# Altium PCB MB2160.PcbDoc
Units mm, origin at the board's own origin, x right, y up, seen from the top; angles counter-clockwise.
Board outline 60 x 59.3 mm, 2 copper layers (Top Layer, Bottom Layer), stack 1.57 mm thick; 35 components, 32 nets, 189 pads, 146 vias.
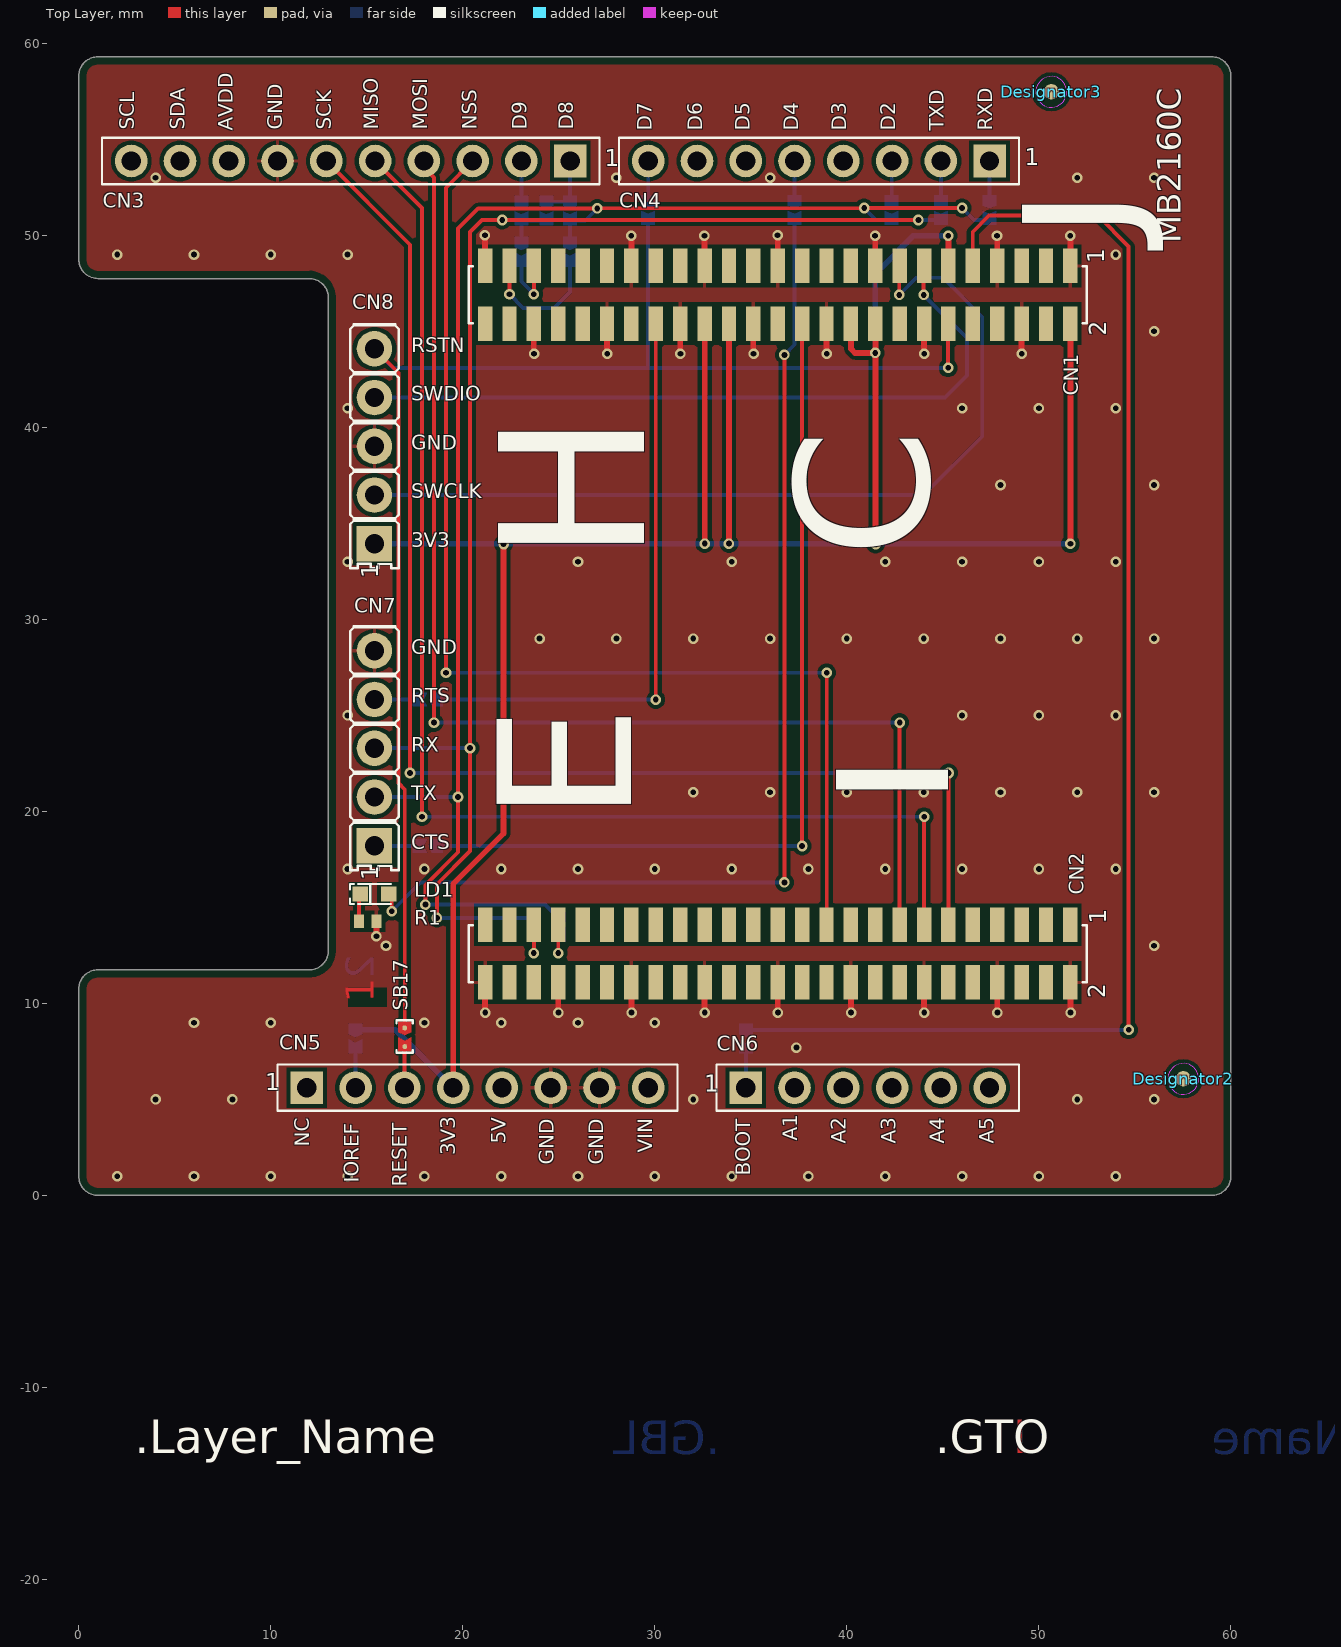
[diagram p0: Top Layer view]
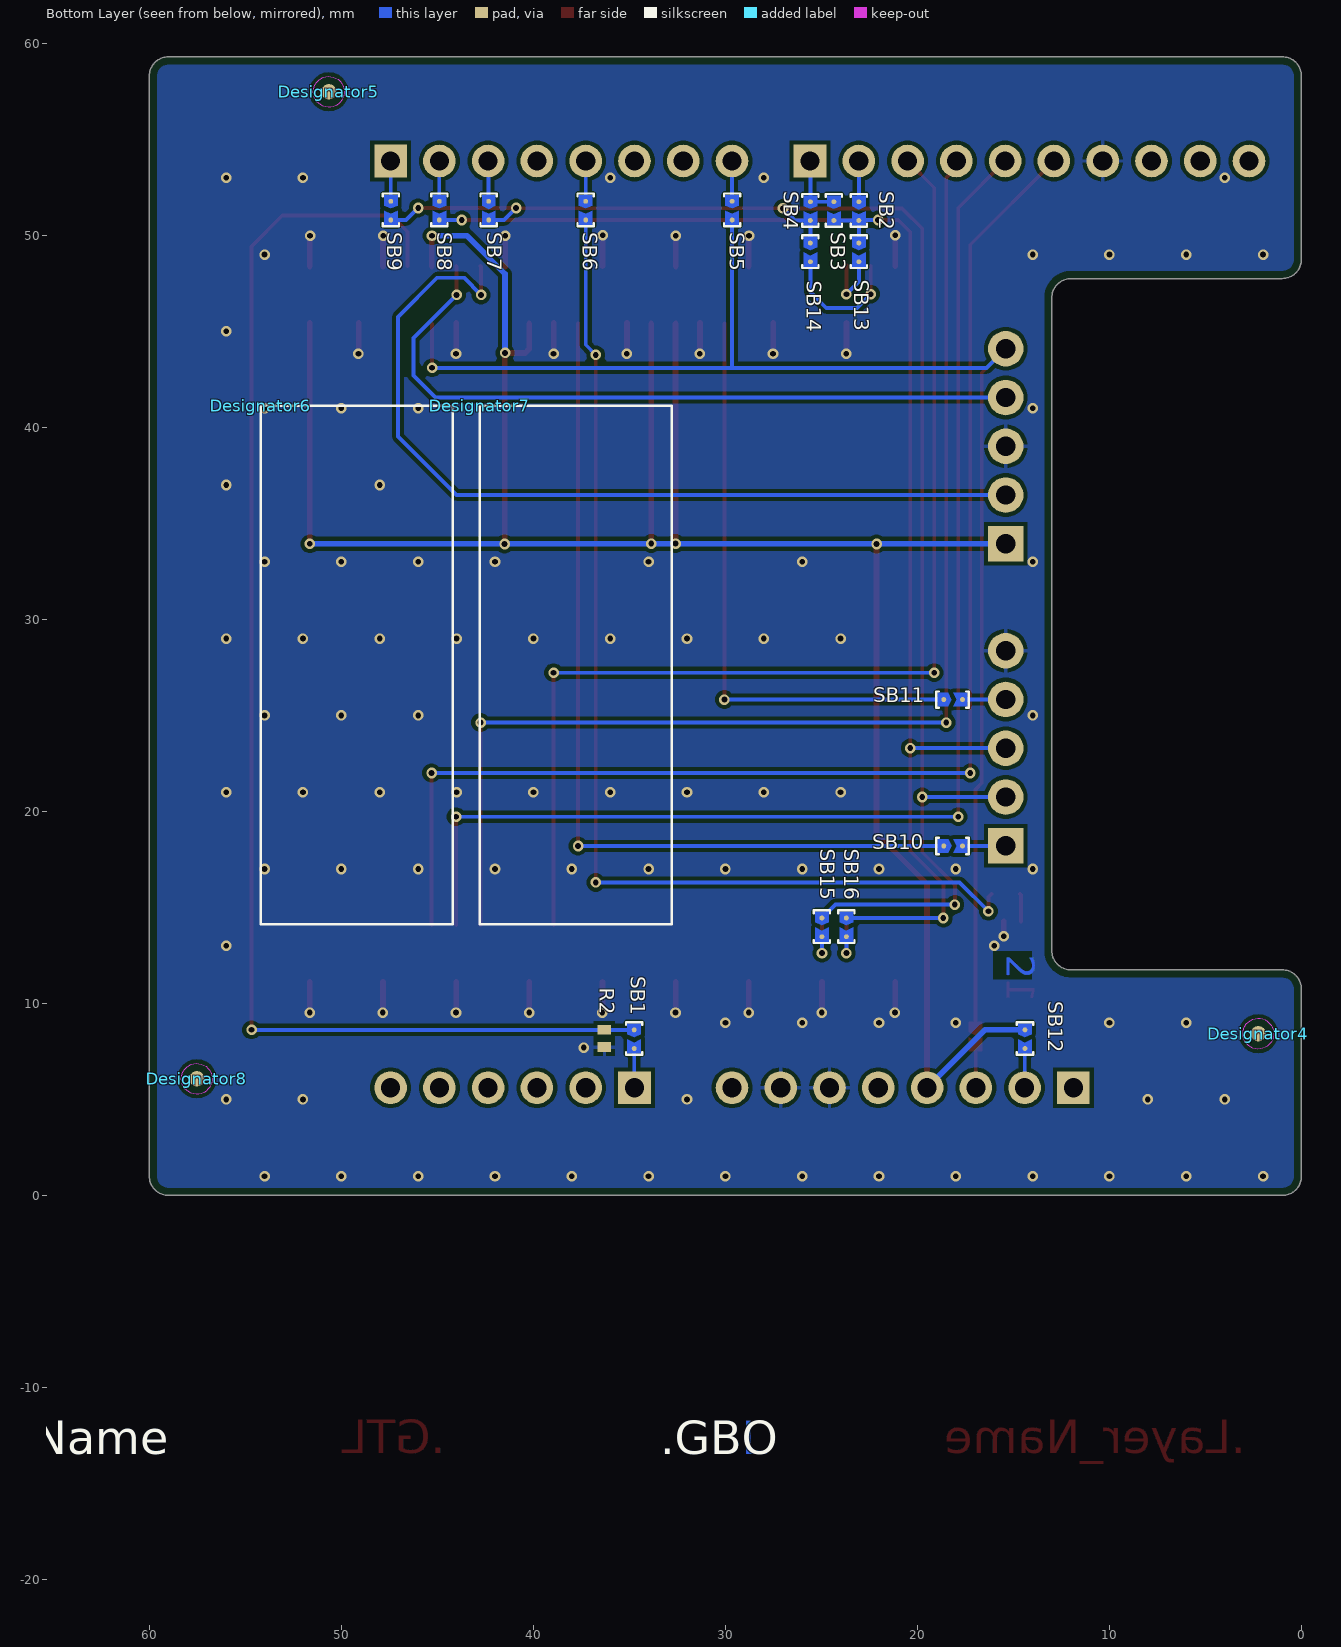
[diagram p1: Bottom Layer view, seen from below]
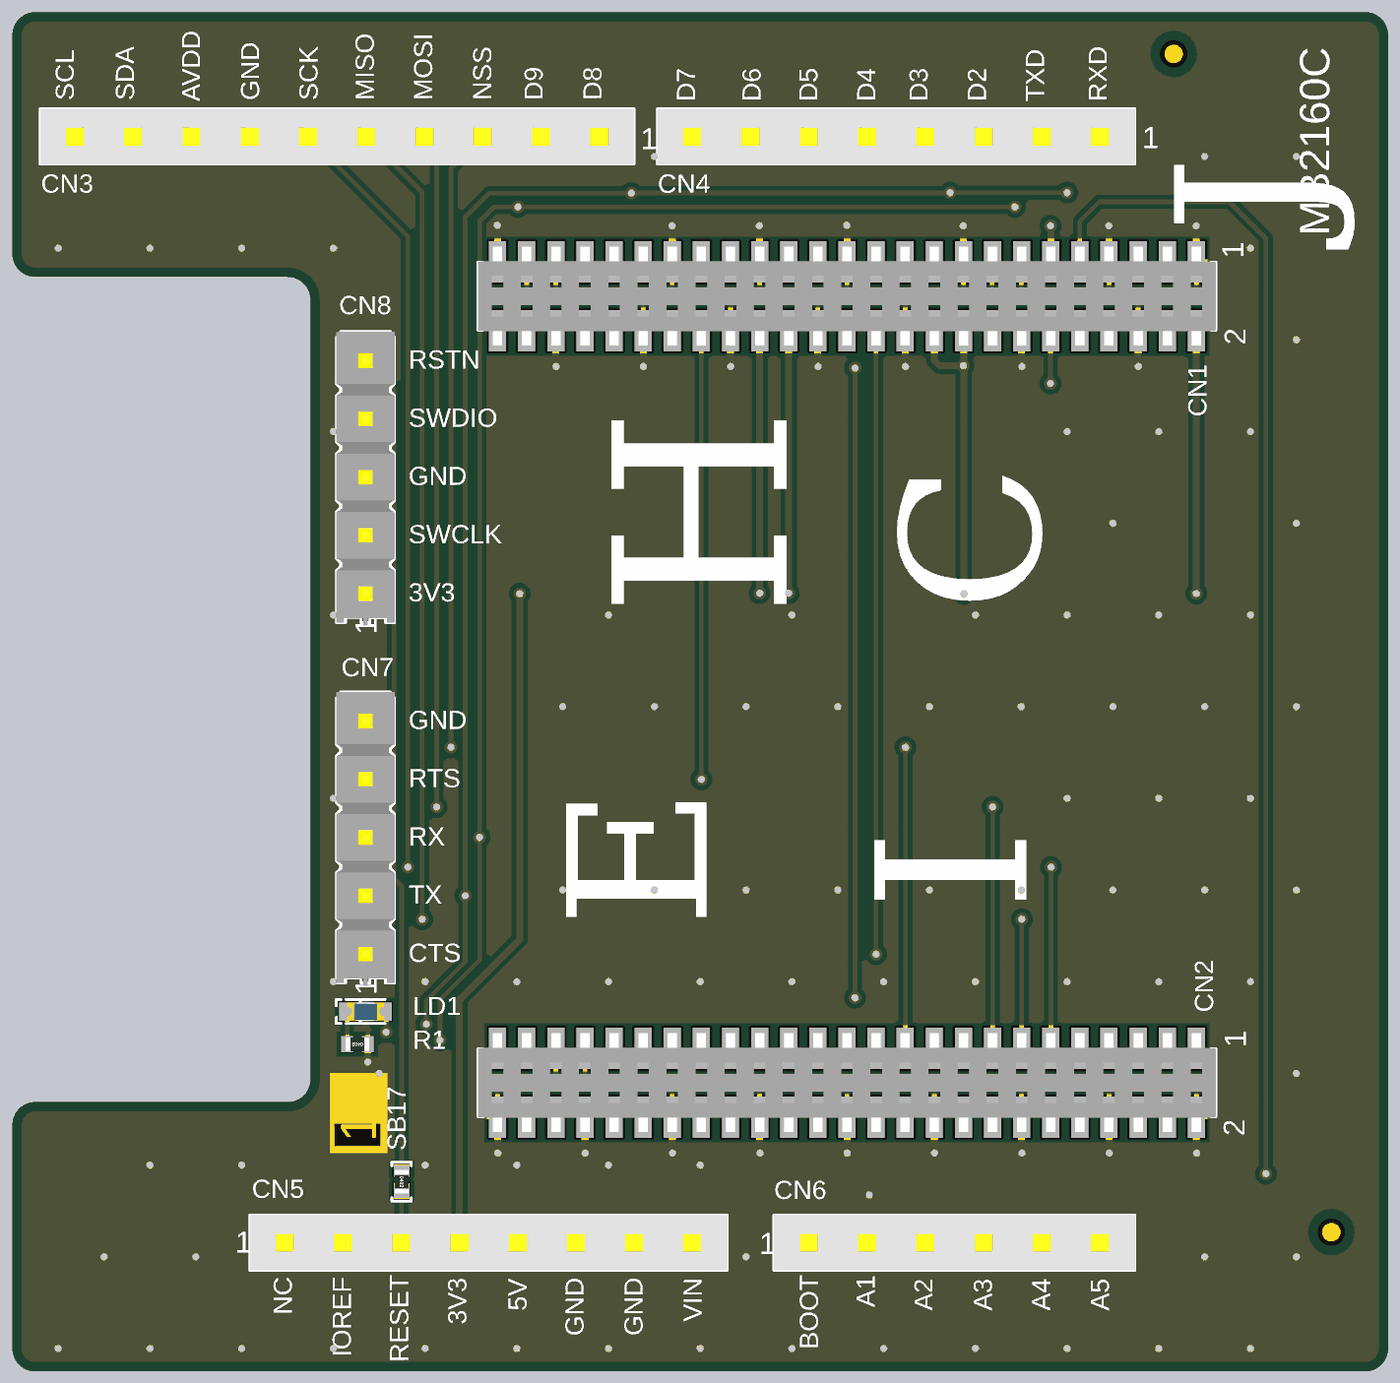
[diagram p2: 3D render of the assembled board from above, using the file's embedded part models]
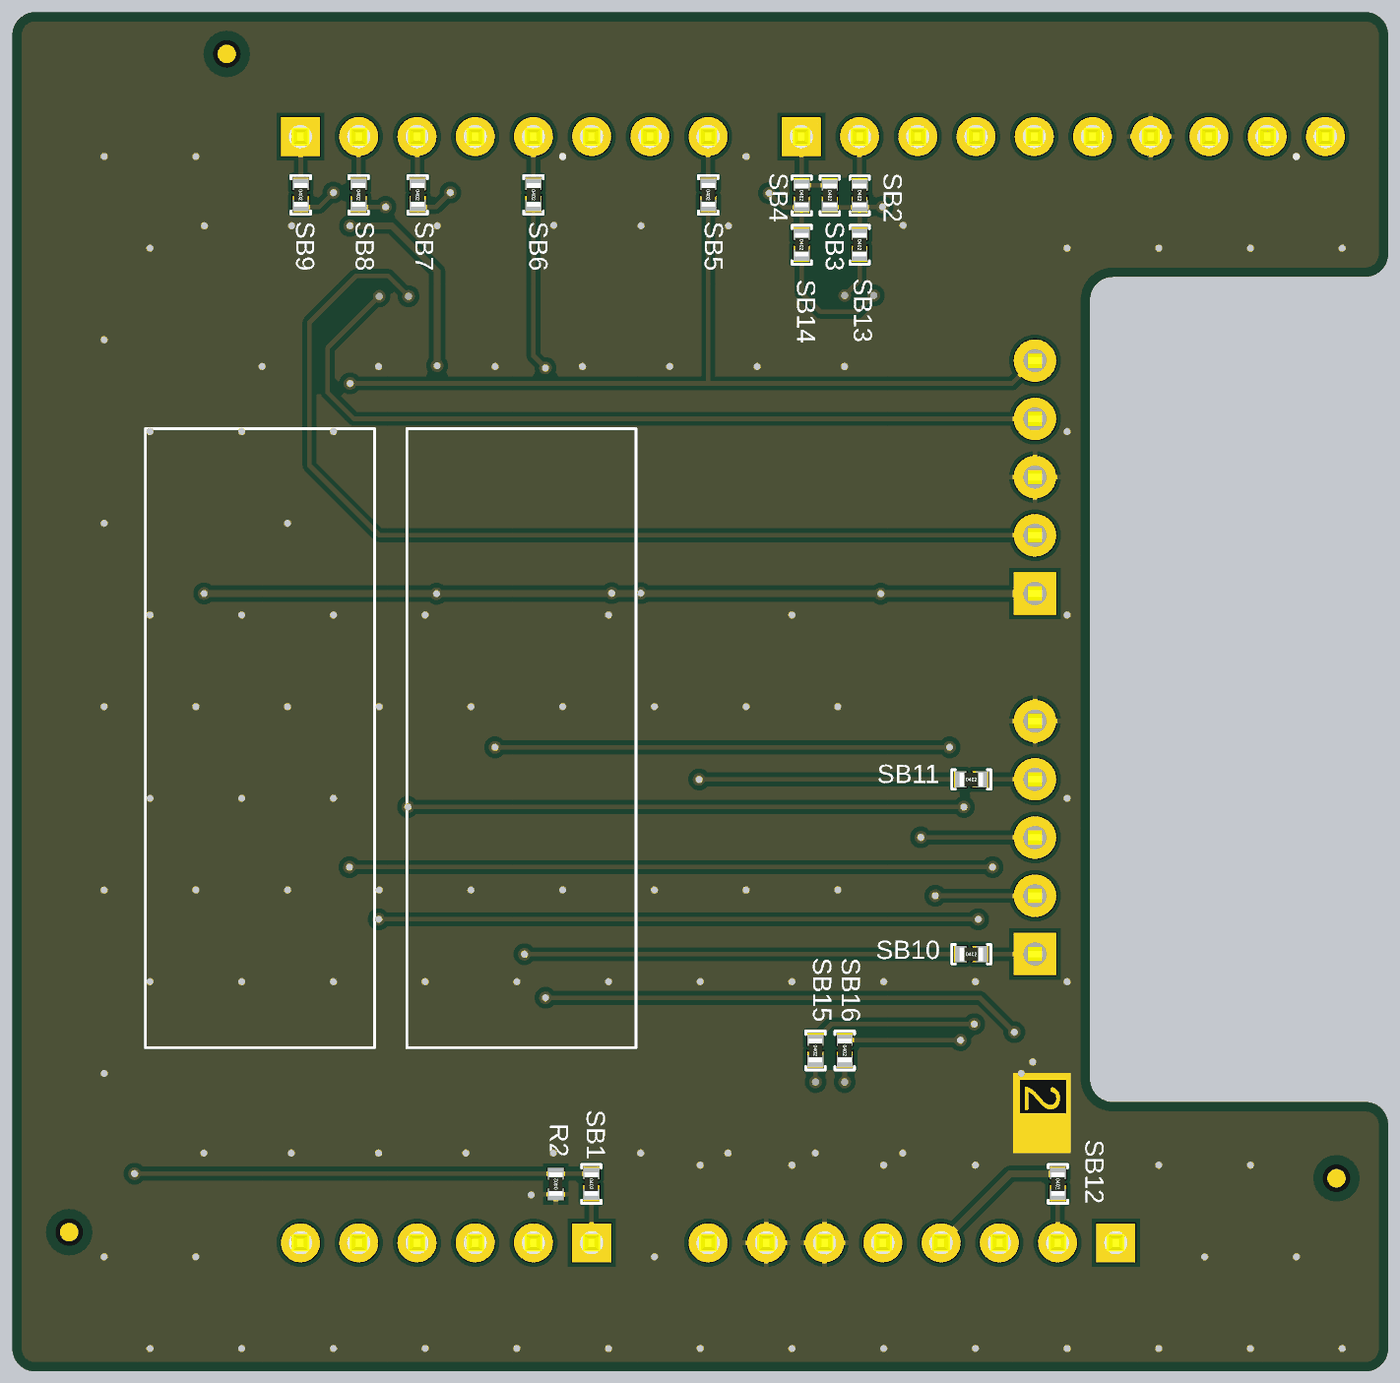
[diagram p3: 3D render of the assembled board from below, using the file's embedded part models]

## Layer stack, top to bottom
Top Solder: solder mask 0.015, Solder Resist, Dk 3.5
Top Layer: signal copper 0.035
Dielectric 1: dielectric 1.5, FR-4, Dk 4.8
Bottom Layer: signal copper 0.035
Bottom Solder: solder mask 0.015, Solder Resist, Dk 3.5

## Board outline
0,1 ccw(c1,1) 1,0 59,0 ccw(c59,1) 60,1 60,58.3 ccw(c59,58.3) 59,59.3 1,59.3 ccw(c1,58.3) 0,58.3 0,48.75 ccw(c1,48.75) 1,47.75 12,47.75 cw(c12,46.75) 13,46.75 13,12.75 cw(c12,12.75) 12,11.75 1,11.75 ccw(c1,10.75) 0,10.75

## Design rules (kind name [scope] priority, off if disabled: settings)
BoardOutlineClearance [All] p1: gap=0.4 ignorepadtopadclearanceinfootprint=FALSE
Clearance [All] p1: gap=0.2 ignorepadtopadclearanceinfootprint=FALSE except(0: Arc-Hole Track-Hole SMDPad-Hole THPad-Hole Via-Hole Fill-Hole Poly-Hole Region-Hole Text-Hole)
ComponentClearance [All] p1: gap=0.2 collisioncheckmode=3 verticalgap=0.2 showdistances=FALSE
HoleSize [All] p1: absolutevalues=TRUE maxlimit=10 minlimit=0.025 maxpercent=80.000 minpercent=20.000
MinimumSolderMaskSliver [All] p1: minsoldermaskwidth=0.1
PlaneConnect [All] p1: planeconnectstyle=Relief reliefexpansion=0.508 reliefentries=4 reliefconductorwidth=0.21 reliefairgap=0.21
PolygonConnect PolygonConnect_via [IsVia] p1: connectstyle=Direct reliefconductorwidth=0.254 reliefentries=4 polygonreliefangle="90 Angle" airgapwidth=0.254
PolygonConnect [All] p2: connectstyle=Relief reliefconductorwidth=0.2 reliefentries=4 polygonreliefangle="90 Angle" airgapwidth=0.2
RoutingVias [All] p1: holewidth=0.3 width=0.55 viastyle="Through Hole" minholewidth=0.3 minwidth=0.55 maxholewidth=0.3 maxwidth=0.55 viatemplateguid#1={C2BB52C7-2357-484C-AD71-DC781CB2D949} viatemplatename#1=v55h30m0mx0(1)
SilkToSilkClearance [All] p1 off: silktosilkclearance=0.254
SilkToSolderMaskClearance [IsPad] p1 off: minsilkscreentomaskgap=0.254 clearancetoexposedcopper=TRUE
SolderMaskExpansion [All] p1: expansion=0.102 istentingtop=FALSE
SupplyNets "Schematic Supply Nets_2" [InNet('IOREF')] p1: voltage=0.000
SupplyNets "Schematic Supply Nets_1" [InNet('3V3')] p2: voltage=0.000
SupplyNets "Schematic Supply Nets" [InNet('GND')] p3: voltage=0.000
Width [All] p1: maxlimit=1 minlimit=0.2 preferedwidth=0.2 minimp=50.000000 maximp=50.000000 favimp=50.000000
24 further rules are at their usual default settings.

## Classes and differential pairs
component class Connectors: CN1 CN2 CN3 CN4 CN5 CN6 CN7 CN8 LD1 R1 R2 SB1 SB2 SB3 SB4 SB5 SB6 SB7 SB8 SB9 SB10 SB11 SB12 SB13 SB14 SB15 SB16 SB17

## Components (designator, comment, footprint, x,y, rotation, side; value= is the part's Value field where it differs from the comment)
CN1 "CLP-125-02-F-D" CON_SAMTEC_CLP-125-02-F-D 36.4,46.907 r270 top value="Socket 25x2"
CN2 "CLP-125-02-F-D" CON_SAMTEC_CLP-125-02-F-D 36.4,12.593 r270 top value="Socket 25x2"
CN3 "Socket 10x1" CON_SAMTEC_SSQ-110-03-F-S 14.162,53.871 r180 top
CN4 "Socket 8x1" CON_SAMTEC_SSQ-108-03-F-S 38.546,53.871 r180 top
CN5 "Socket 8x1" CON_SAMTEC_SSQ-108-03-F-S 20.766,5.611 r0 top
CN6 "Socket 6x1" CON_SAMTEC_SSQ-106-03-F-S 41.086,5.611 r0 top
CN7 "Header 5x1" CON_SAMTEC_TSW-105-07-X-S 15.4,23.29 r90 top
CN8 "Header 5x1" CON_SAMTEC_TSW-105-07-X-S 15.4,39.015 r90 top
Designator2 "Comment" MIRE_PLACE_SMD_0P8MM 57.525,6.075 r180 top
Designator3 "Comment" MIRE_PLACE_SMD_0P8MM 50.65,57.475 r180 top
Designator4 "Comment" MIRE_PLACE_SMD_0P8MM 2.25,8.425 r0 bottom
Designator5 "Comment" MIRE_PLACE_SMD_0P8MM 50.65,57.475 r0 bottom
Designator6 "Comment" LOGO_ETIQUETTE 54.2,41.125 r270 bottom
Designator7 "Comment" LOGO_ETIQUETTE 42.8,41.125 r270 bottom locked
Designator8 "Comment" MIRE_PLACE_SMD_0P8MM 57.525,6.075 r0 bottom
LD1 "LED_blue" LED_0603_OSRAM_LB-Q39G-L2OO-35-1_BLUE_1A2K_H0P4 15.4,15.7 r180 top value=Blue
R1 "Resistor" R0402 15.05,14.275 r180 top value=680R
R2 "Resistor" R0402 36.3,8.175 r90 bottom value=100K
SB1 "SB_ON" SOLDER-BRIDGE_R0402-0R 34.75,8.175 r270 bottom value=0R
SB2 "SB_ON" SOLDER-BRIDGE_R0402-0R 23.05,51.3 r270 bottom value=0R
SB3 "SB_ON" SOLDER-BRIDGE_R0402-0R 24.35,51.3 r270 bottom value=0R
SB4 "SB_ON" SOLDER-BRIDGE_R0402-0R 25.575,51.3 r270 bottom value=0R
SB5 "SB_ON" SOLDER-BRIDGE_R0402-0R 29.65,51.325 r270 bottom value=0R
SB6 "SB_ON" SOLDER-BRIDGE_R0402-0R 37.275,51.325 r270 bottom value=0R
SB7 "SB_ON" SOLDER-BRIDGE_R0402-0R 42.325,51.325 r270 bottom value=0R
SB8 "SB_ON" SOLDER-BRIDGE_R0402-0R 44.9,51.325 r270 bottom value=0R
SB9 "SB_ON" SOLDER-BRIDGE_R0402-0R 47.425,51.325 r270 bottom value=0R
SB10 "SB_ON" SOLDER-BRIDGE_R0402-0R 18.175,18.2 r180 bottom value=0R
SB11 "SB_ON" SOLDER-BRIDGE_R0402-0R 18.175,25.825 r180 bottom value=0R
SB12 "SB_ON" SOLDER-BRIDGE_R0402-0R 14.4,8.175 r270 bottom value=0R
SB13 "SB_ON" SOLDER-BRIDGE_R0402-0R 23.05,49.15 r270 bottom value=0R
SB14 "SB_ON" SOLDER-BRIDGE_R0402-0R 25.575,49.15 r270 bottom value=0R
SB15 "SB_ON" SOLDER-BRIDGE_R0402-0R 24.975,14 r270 bottom value=0R
SB16 "SB_ON" SOLDER-BRIDGE_R0402-0R 23.7,14 r270 bottom value=0R
SB17 "SB_ON" SOLDER-BRIDGE_R0402-0R 16.975,8.275 r270 top value=0R

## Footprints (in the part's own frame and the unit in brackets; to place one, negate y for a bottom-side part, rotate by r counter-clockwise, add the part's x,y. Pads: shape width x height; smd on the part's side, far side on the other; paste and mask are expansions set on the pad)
CON_SAMTEC_CLP-125-02-F-D [mm] "MCD-02705"
  rect 1.8x0.75 smd: 1(-1.5,15.24) 2(1.5,15.24) 3(-1.5,13.97) 4(1.5,13.97) 5(-1.5,12.7) 6(1.5,12.7) 7(-1.5,11.43) 8(1.5,11.43) 9(-1.5,10.16) 10(1.5,10.16) 11(-1.5,8.89) 12(1.5,8.89) 13(-1.5,7.62) 14(1.5,7.62) 15(-1.5,6.35) 16(1.5,6.35) 17(-1.5,5.08) 18(1.5,5.08) 19(-1.5,3.81) 20(1.5,3.81) 21(-1.5,2.54) 22(1.5,2.54) 23(-1.5,1.27) 24(1.5,1.27) 25(-1.5,0) 26(1.5,0) 27(-1.5,-1.27) 28(1.5,-1.27) 29(-1.5,-2.54) 30(1.5,-2.54) 31(-1.5,-3.81) 32(1.5,-3.81) 33(-1.5,-5.08) 34(1.5,-5.08) 35(-1.5,-6.35) 36(1.5,-6.35) 37(-1.5,-7.62) 38(1.5,-7.62) 39(-1.5,-8.89) 40(1.5,-8.89) 41(-1.5,-10.16) 42(1.5,-10.16) 43(-1.5,-11.43) 44(1.5,-11.43) 45(-1.5,-12.7) 46(1.5,-12.7) 47(-1.5,-13.97) 48(1.5,-13.97) 49(-1.5,-15.24) 50(1.5,-15.24)
  silkscreen extent -1.48,-16.09 1.49,16.09, body extent -2.16,-16.09 2.16,16.09, height 2.27
CON_SAMTEC_SSQ-106-03-F-S [mm] "MCD-02623"
  rect 1.7x1.7 hole 1 mask+0.05: 1(-6.35,0)
  round 1.7 hole 1 mask+0.05: 2(-3.81,0) 3(-1.27,0) 4(1.27,0) 5(3.81,0) 6(6.35,0)
  silkscreen extent -7.88,-1.21 7.88,1.21, body extent -7.87,-1.21 7.87,1.21, height 8.51
CON_SAMTEC_SSQ-108-03-F-S [mm] "MCD-02624"
  rect 1.7x1.7 hole 1 mask+0.05: 1(-8.89,0)
  round 1.7 hole 1 mask+0.05: 2(-6.35,0) 3(-3.81,0) 4(-1.27,0) 5(1.27,0) 6(3.81,0) 7(6.35,0) 8(8.89,0)
  silkscreen extent -10.41,-1.21 10.41,1.21, body extent -10.41,-1.21 10.41,1.21, height 8.51
CON_SAMTEC_SSQ-110-03-F-S [mm] "MCD-02625"
  rect 1.7x1.7 hole 1 mask+0.05: 1(-11.43,0)
  round 1.7 hole 1 mask+0.05: 2(-8.89,0) 3(-6.35,0) 4(-3.81,0) 5(-1.27,0) 6(1.27,0) 7(3.81,0) 8(6.35,0) 9(8.89,0) 10(11.43,0)
  silkscreen extent -12.95,-1.21 12.95,1.21, body extent -12.95,-1.21 12.95,1.21, height 8.51
CON_SAMTEC_TSW-105-07-X-S [mm] "MCD-02060"
  rect 1.85x1.85 hole 1 mask+0.05: 1(-5.08,0)
  round 1.85 hole 1 mask+0.05: 2(-2.54,0) 3(0,0) 4(2.54,0) 5(5.08,0)
  silkscreen extent -6.35,-1.27 6.35,1.27, body extent -6.48,-1.27 6.35,1.27, height 8.38
LED_0603_OSRAM_LB-Q39G-L2OO-35-1_BLUE_1A2K_H0P4 [mm]
  rect 0.8x0.8 smd mask+0.05: 1(-0.75,0) 2(0.75,0)
  silkscreen extent -0.85,-0.53 1.28,0.53, body extent -0.85,-0.45 0.85,0.45, height 0.6
LOGO_ETIQUETTE [mm]
  silkscreen extent 0,0 27,10
MIRE_PLACE_SMD_0P8MM [mm]
  round 0.8 smd paste-10 mask+0.2: 1(0,0)
  Top Layer keep-out circle w0.01: c0,0 r0.804
R0402 [mm]
  rect 0.51x0.7 smd mask+0.05: 1(-0.45,0) 2(0.45,0)
  body extent -0.52,-0.3 0.52,0.3, height 0.4
SOLDER-BRIDGE_R0402-0R [mil] "MCD-01619"
  round 10 smd paste-393.7: 1(-17.72,0) 2(20.67,0)
  Top Layer region: 1.48,13.78 8.37,0 1.48,-13.78 30.51,-13.78 30.51,13.78
  Top Layer region: -30.51,-13.78 -30.51,13.78 -8.86,13.78 -2.95,0 -8.86,-13.78
  silkscreen extent -33,-17 33,17, body extent -20,-12 20,12, height 14

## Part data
CN1 CN2: library part MCD-02705, "Socket, 25x2, 1.27mm, VR, SMD, T=2.29mm", Manufacturer=SAMTEC
CN3: library part MCD-02625, "Socket, 10x1, 2.54mm, VR, TH, T=8.51mm/10mm", Manufacturer=SAMTEC, Manufacturer_Part_Number=SSQ-110-03-F-S
CN4 CN5: library part MCD-02624, "Socket, 8x1, 2.54mm, VR, TH, T=8.51mm/10mm", Manufacturer=SAMTEC, Manufacturer_Part_Number=SSQ-108-03-F-S
CN6: library part MCD-02623, "Socket, 6x1, 2.54mm, VR, TH, T=8.51mm/10mm", Manufacturer=SAMTEC, Manufacturer_Part_Number=SSQ-106-03-F-S
CN7 CN8: library part MCD-02060, "Header, 5x1, 2.54mm, VR, TH, T=5.84mm/2.54mm", Manufacturer=SAMTEC, Manufacturer_Part_Number=TSW-105-07-G-S
LD1: library part MCD-00585, "LED, Blue, 2V85, 5mA, 0603", Manufacturer="OSRAM OPTO SEMICONDUCTORS", Manufacturer_Part_Number="LB Q39G-L2OO-35-1", Package=0603
R1: library part MCD-00507, "Resistor, 680R, 0402, +/-1%, 1/16W", Manufacturer=YAGEO, Manufacturer_Part_Number=RC0402FR-07680RL, Package=0402
R2: library part MCD-00059, "Resistor, 100K, 0402, +/-1%, 1/16W", Manufacturer=YAGEO, Manufacturer_Part_Number=RC0402FR-07100KL, Package=0402
SB1 SB2 SB3 SB4 SB5 SB6 SB7 SB8 SB9 SB10 SB11 SB12 SB13 SB14 SB15 SB16 SB17: library part MCD-01618, "Resistor, 0R, SB0402, 5%, 0.063W", Manufacturer=YAGEO, Manufacturer_Part_Number=RC0402JR-070RL, Package=0402

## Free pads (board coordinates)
  round 0.508 on Mech16: 1(14.573,-20.356) 1(63.421,-20.356)

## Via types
v1: diameter 0.55, hole 0.3, Top Layer to Bottom Layer, tented both sides, 146 vias

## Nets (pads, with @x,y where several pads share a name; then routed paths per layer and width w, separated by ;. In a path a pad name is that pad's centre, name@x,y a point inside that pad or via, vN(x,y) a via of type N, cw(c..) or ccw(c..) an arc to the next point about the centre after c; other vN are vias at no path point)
3V3: CN1.2 CN1.11 CN1.18 CN1.20 CN1.30 CN1.32 CN5.4 CN8.1 SB12.1 | length 130.6
  Top Layer w0.3: CN5.4 19.496,16.221 22.125,18.85 v1(22.125,33.925) ; CN1.32 32.595,45.402 v1(32.595,33.95) ; v1(33.86,33.95) CN1.30 ; CN1.20 40.21,44.09 40.425,43.875 v1(41.475,43.875) ; CN1.18 41.49,45.397 41.49,33.935 v1(41.5,33.925) ; CN1.11@45.29,48.383 CN1.11 v1@45.29,49.966 ; v1(51.64,33.935) CN1.2 CN1.2@51.64,45.431
  Bottom Layer w0.3: 14.7,8.625 16.482,8.625 CN5.4 ; CN8.1 v1(51.64,33.935) ; v1(41.475,43.875) 41.475,47.994 43.457,49.976 v1(45.28,49.976)
BOOT: CN1.9 R2.2 SB1.1 | length 71.6
  Top Layer w0.2: CN1.9 46.56,50.185 47.4,51.025 53.075,51.025 54.675,49.425 v1(54.675,8.625)
  Bottom Layer w0.2: SB1.1 v1(54.675,8.625)
GND: CN1.1 CN1.6 CN1.7 CN1.14 CN1.17 CN1.22 CN1.25 CN1.28 CN1.31 CN1.34 CN1.37 CN1.40 CN1.46 CN1.49 CN2.2 CN2.8 CN2.14 CN2.20 CN2.26 CN2.32 CN2.38 CN2.44 CN2.50 CN3.7 CN5.6 CN5.7 CN7.5 CN8.3 R1.1 R2.1 | length 37.5
  Top Layer w0.3: v1(15.5,13.5) R1.1 ; v1(21.15,50) 21.16,49.99 CN1.49 ; CN2.50@21.16,11.117 21.16,9.534 v1(21.17,9.524) ; CN1.46@23.7,45.431 23.7,43.848 v1(23.71,43.838) ; CN2.44@24.97,11.117 24.97,9.534 v1(24.98,9.524) ; CN1.40@27.51,45.431 27.51,43.848 v1(27.52,43.838) ; v1(28.77,49.976) 28.78,49.966 CN1.37@28.78,48.383 ; CN2.38@28.78,11.117 28.78,9.534 v1(28.79,9.524) ; CN1.34@31.32,45.431 31.32,43.848 v1(31.33,43.838) ; v1(32.58,49.976) 32.59,49.966 CN1.31@32.59,48.383 ; CN2.32@32.59,11.117 32.59,9.534 v1(32.6,9.524) ; CN1.28@35.13,45.431 35.13,43.848 v1(35.14,43.838) ; v1(36.39,50) 36.4,49.99 CN1.25 ; CN2.26@36.4,11.117 36.4,9.534 v1(36.41,9.524) ; CN1.22@38.94,45.431 38.94,43.848 v1(38.95,43.838) ; CN2.20@40.21,11.117 40.21,9.534 v1(40.22,9.524) ; v1(41.47,49.976) 41.48,49.966 CN1.17@41.48,48.383 ; CN2.14@44.02,11.117 44.02,9.534 v1(44.03,9.524) ; CN1.14@44.02,45.431 44.02,43.848 v1(44.03,43.838) ; v1(47.82,49.976) 47.83,49.966 CN1.7@47.83,48.383 ; CN2.8@47.83,11.117 47.83,9.534 v1(47.84,9.524) ; CN1.6@49.1,45.431 49.1,43.848 v1(49.11,43.838) ; v1(51.63,49.976) 51.64,49.966 CN1.1@51.64,48.383 ; CN2.2@51.64,11.117 51.64,9.534 v1(51.65,9.524)
  other v1: 2,1 6,1 10,1 14,1 18,1 22,1 26,1 30,1 34,1 38,1 42,1 46,1 50,1 54,1 4,5 8,5 32,5 52,5 56,5 37.375,7.7 6,9 10,9 18,9 22,9 26,9 30,9 16,13 56,13 14,17 18,17 22,17 26,17 30,17 34,17 38,17 42,17 46,17 50,17 54,17 24,21 28,21 32,21 36,21 40,21 44,21 48,21 52,21 56,21 14,25 46,25 50,25 54,25 24,29 28,29 32,29 36,29 40,29 44,29 48,29 52,29 56,29 14,33 26,33 34,33 42,33 46,33 50,33 54,33 48,37 56,37 14,41 46,41 50,41 54,41 56,45 2,49 6,49 10,49 14,49 54,49 4,53 28,53 36,53 52,53 56,53
IOREF: CN5.2 SB12.2 | length 2
  Bottom Layer w0.2: SB12.2 14.408,7.642 14.408,5.619 CN5.2
LED: LD1.1 SB6.2 | length 56.8
  Top Layer w0.2: LD1.1 16.3,15.55 v1(16.3,14.8) ; v1(36.75,16.3) v1(36.75,43.775)
  Bottom Layer w0.2: v1(16.3,14.8) 17.8,16.3 v1(36.75,16.3) ; v1(36.75,43.775) 37.275,44.3 SB6.2
MISO: CN2.13 CN3.5 | length 66.9
  Top Layer w0.2: CN3.5 17.875,51.428 v1(17.875,19.725) ; CN2.13 44.025,14.098 v1(44.025,19.725)
  Bottom Layer w0.2: v1(17.875,19.725) v1(44.025,19.725)
MOSI: CN2.15 CN3.4 | length 64.2
  Top Layer w0.2: CN3.4 17.972,53.532 18.5,53.004 v1(18.5,24.625) ; CN2.15 v1(42.75,24.625)
  Bottom Layer w0.2: v1(18.5,24.625) v1(42.75,24.625)
NetCN1_24: CN1.24 SB10.1 | length 46.3
  Top Layer w0.2: v1(37.67,18.2) CN1.24
  Bottom Layer w0.2: SB10.1 v1@37.675,18.2
NetCN1_36: CN1.36 SB11.1 | length 31
  Top Layer w0.2: v1(30.05,25.825) CN1.36
  Bottom Layer w0.2: SB11.1 v1(30.05,25.825)
NetCN1_45: CN1.45 SB13.2 | length 3.4
  Top Layer w0.2: v1(23.7,46.938) CN1.45 CN1.45@23.7,48.431
  Bottom Layer w0.2: SB13.2 23.05,47.588 v1(23.7,46.938)
NetCN1_47: CN1.47 SB14.2 | length 6.8
  Top Layer w0.2: v1(22.43,46.938) CN1.47
  Bottom Layer w0.2: v1(22.43,46.938) 23.143,46.225 24.75,46.225 25.575,47.05 SB14.2
NetCN2_43: CN2.43 SB15.2 | length 2.3
  Top Layer w0.2: v1(24.97,12.624) CN2.43
  Bottom Layer w0.2: v1(24.97,12.624) 24.973,12.626 24.973,13.473 SB15.2
NetCN2_45: CN2.45 SB16.2 | length 2.3
  Top Layer w0.2: v1(23.7,12.624) CN2.45
  Bottom Layer w0.2: v1(23.7,12.624) SB16.2
NetCN3_1: CN3.1 SB3.1 SB4.1 | length 3.4
  Bottom Layer w0.2: SB3.1 SB4.1 25.575,53.854 CN3.1
NetCN3_2: CN3.2 SB2.1 | length 2.1
  Bottom Layer w0.2: SB2.1 SB2.1 23.051,53.87 CN3.2
NetCN4_1: CN4.1 SB9.1 | length 2.1
  Bottom Layer w0.2: SB9.1 47.425,53.86 CN4.1
NetCN4_2: CN4.2 SB8.1 | length 2.1
  Bottom Layer w0.2: CN4.2 44.898,53.869 44.898,51.777 SB8.1
NetCN4_3: CN4.3 SB7.1 | length 2.1
  Bottom Layer w0.2: SB7.1 42.335,51.785 42.335,53.85 CN4.3
NetCN4_5: CN4.5 SB6.1 | length 2.1
  Bottom Layer w0.2: SB6.1@37.276,51.775 CN4.5
NetCN4_8: CN4.8 SB5.1 | length 2.1
  Bottom Layer w0.2: SB5.1 29.653,51.778 29.653,53.868 CN4.8
NetCN5_3: CN5.3 SB17.2 | length 2.1
  Top Layer w0.2: CN5.3 16.966,5.62 16.966,7.741 SB17.2
NetCN6_1: CN6.1 SB1.2 | length 2
  Bottom Layer w0.2: CN6.1 34.75,5.625 SB1.2
NetLD1_2: LD1.2 R1.2 | length 1.4
  Top Layer w0.2: R1.2 14.6,15.65 LD1.2
NSS: CN2.21 CN3.3 | length 60.2
  Top Layer w0.2: v1(19.125,27.225) 19.125,52.48 20.512,53.867 CN3.3 ; CN2.21 38.95,14.103 v1(38.95,27.225)
  Bottom Layer w0.2: v1(19.125,27.225) v1(38.95,27.225)
RSTN: CN1.12 CN8.5 SB5.2 SB17.1 | length 76.3
  Top Layer w0.2: CN8.5 16.65,42.845 16.65,21.475 16.975,21.15 SB17.1 ; v1(45.275,43.1) 45.275,45.392 CN1.12
  Bottom Layer w0.2: CN8.5 16.395,43.1 29.65,43.1 ; SB5.2 29.65,43.1 ; v1(45.275,43.1) 29.65,43.1
SCk: CN2.11 CN3.6 | length 69.6
  Top Layer w0.2: CN3.6 17.25,49.513 v1@17.25,22.013 ; CN2.11 45.3,14.103 v1(45.3,22)
  Bottom Layer w0.2: v1(17.25,22) v1(45.3,22)
SWCLK: CN1.15 CN8.2 | length 46.2
  Top Layer w0.2: v1(42.725,46.9) 42.725,48.382 CN1.15
  Bottom Layer w0.2: CN8.2 44,36.475 47.05,39.525 47.05,45.75 45.004,47.796 43.621,47.796 v1(42.725,46.9)
SWDIO: CN1.13 CN8.4 | length 38
  Top Layer w0.2: v1(44,46.9) 44,48.387 CN1.13
  Bottom Layer w0.2: CN8.4 45.105,41.555 46.25,42.7 46.25,44.65 v1(44,46.9)
T_UART_CTS: CN7.1 SB10.2 | length 2.3
  Bottom Layer w0.2: CN7.1 15.41,18.2 SB10.2
T_UART_RTS: CN7.4 SB11.2 | length 2.3
  Bottom Layer w0.2: CN7.4 15.402,25.827 17.647,25.827 SB11.2
T_UART_RX: CN7.3 SB2.2 SB3.2 SB8.2 SB13.1 SB16.1 | length 74.7
  Top Layer w0.2: v1(18.65,14.45) 18.65,16.209 20.375,17.934 v1(20.375,23.3) 20.375,50.175 21,50.8 v1(22.05,50.8) 23.7,50.8 v1(43.725,50.8)
  Bottom Layer w0.2: CN7.3 15.405,23.295 20.37,23.295 v1(20.375,23.3) ; v1(18.65,14.45) SB16.1 ; v1(22.05,50.8) 22.987,50.8 23.001,50.785 23.04,50.785 SB2.2 ; SB13.1 SB2.2 ; SB3.2 SB2.2 ; v1(43.725,50.8) SB8.2
T_UART_TX: CN7.2 SB4.2 SB7.2 SB9.2 SB14.1 SB15.1 | length 80.4
  Top Layer w0.2: v1(18.05,15.15) 18.05,16.175 19.75,17.875 v1(19.75,20.75) 19.75,50.35 20.8,51.4 v1(27,51.4) 27.013,51.412 40.887,51.412 v1(40.9,51.425) v1(46,51.425)
  Bottom Layer w0.2: CN7.2 v1(19.75,20.75) ; v1(18.05,15.15) 24.275,15.15 SB15.1 ; SB14.1 SB4.2 26.375,50.775 v1(27,51.4) ; v1(40.9,51.425) 41.525,50.8 SB7.2 ; v1(46,51.425) 46.625,50.8 SB9.2
pads on no net: CN1.3 CN1.4 CN1.5 CN1.8 CN1.10 CN1.16 CN1.19 CN1.21 CN1.23 CN1.26 CN1.27 CN1.29 CN1.33 CN1.35 CN1.38 CN1.39 CN1.41 CN1.42 CN1.43 CN1.44 CN1.48 CN1.50 CN2.1 CN2.3 CN2.4 CN2.5 CN2.6 CN2.7 CN2.9 CN2.10 CN2.12 CN2.16 CN2.17 CN2.18 CN2.19 CN2.22 CN2.23 CN2.24 CN2.25 CN2.27 CN2.28 CN2.29 CN2.30 CN2.31 CN2.33 CN2.34 CN2.35 CN2.36 CN2.37 CN2.39 CN2.40 CN2.41 CN2.42 CN2.46 CN2.47 CN2.48 CN2.49 CN3.8 CN3.9 CN3.10 CN4.4 CN4.6 CN4.7 CN5.1 CN5.5 CN5.8 CN6.2 CN6.3 CN6.4 CN6.5 CN6.6 Designator2.1 Designator3.1 Designator4.1 Designator5.1 Designator8.1

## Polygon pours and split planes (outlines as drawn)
GND on Bottom Layer "GND" (solid, remove dead copper, pour order 0): -1.225,61.7 -1.225,-2.35 61.95,-2.35 61.95,61.7
GND on Top Layer "GND" (solid, remove dead copper, pour order 1): -1.225,61.7 -1.225,-2.35 61.95,-2.35 61.95,61.7

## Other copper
Top Layer:
  text "1" at 15.85,10.025 h2.5 r90
  text ".Layer_Name" at 2.903,-14.008 h3
  text ".GTL" at 44.598,-14.008 h3
Bottom Layer:
  text "2" at 15.85,12.525 h2.5 r90
  text ".GBL" at 33.395,-14.04 h3
  text ".Layer_Name" at 74.709,-14.04 h3

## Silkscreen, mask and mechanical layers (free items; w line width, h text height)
Top Overlay:
  text "SCL" at 3.15,55.5 h1.3 r90
  text "SDA" at 5.775,55.5 h1.3 r90
  text "GND" at 10.85,55.5 h1.3 r90
  text "SCK" at 13.4,55.5 h1.3 r90
  text "MISO" at 15.85,55.5 h1.3 r90
  text "MOSI" at 18.4,55.5 h1.3 r90
  text "NSS" at 20.975,55.5 h1.3 r90
  text "D9" at 23.6,55.5 h1.3 r90
  text "D8" at 26,55.5 h1.3 r90
  text "AVDD" at 8.275,55.45 h1.3 r90
  text "D7" at 30.1,55.45 h1.3 r90
  text "D6" at 32.725,55.45 h1.3 r90
  text "D5" at 35.2,55.45 h1.3 r90
  text "D4" at 37.725,55.45 h1.3 r90
  text "D3" at 40.225,55.45 h1.3 r90
  text "D2" at 42.775,55.45 h1.3 r90
  text "TXD" at 45.3,55.45 h1.3 r90
  text "RXD" at 47.825,55.45 h1.3 r90
  text "J" at 56.825,49.7 h12 r90
  text "MB2160C" at 57.8,49.6 h2.1 r90
  text "RSTN" at 17.325,43.66 h1.3
  text "SWDIO" at 17.325,41.12 h1.3
  text "GND" at 17.325,38.58 h1.3
  text "SWCLK" at 17.325,36.04 h1.3
  text "3V3" at 17.325,33.5 h1.3
  text "C" at 46.55,33.2 h12 r90
  text "H" at 32.3,32.95 h15 r90
  text "GND" at 17.325,27.935 h1.3
  text "RTS" at 17.325,25.395 h1.3
  text "RX" at 17.325,22.855 h1.3
  text "TX" at 17.325,20.315 h1.3
  text "I" at 47.725,20.125 h13 r90
  text "E" at 31.075,19.425 h12 r90
  text "CTS" at 17.325,17.775 h1.3
  text "A1" at 37.675,2.85 h1.3 r90
  text "5V" at 22.5,2.7 h1.3 r90
  text "A2" at 40.2,2.7 h1.3 r90
  text "A3" at 42.8,2.7 h1.3 r90
  text "A4" at 45.325,2.7 h1.3 r90
  text "A5" at 47.9,2.7 h1.3 r90
  text "NC" at 12.275,2.525 h1.3 r90
  text "VIN" at 30.125,2.225 h1.3 r90
  text "3V3" at 19.875,2.1 h1.3 r90
  text "GND" at 25,1.6 h1.3 r90
  text "GND" at 27.575,1.606 h1.3 r90
  text "BOOT" at 35.225,1.025 h1.3 r90
  text "IOREF" at 14.85,0.675 h1.3 r90
  text "RESET" at 17.35,0.45 h1.3 r90
  text ".Layer_Name" at 2.903,-14.008 h3
  text ".GTO" at 44.598,-14.008 h3
Bottom Overlay:
  text ".GBO" at 33.395,-14.04 h3
  text ".Layer_Name" at 74.709,-14.04 h3
Top Paste:
  text ".Layer_Name" at 2.876,-13.998 h3
  text ".GTP" at 44.571,-13.998 h3
Bottom Paste:
  text ".GBP" at 33.286,-14.025 h3
  text ".Layer_Name" at 74.6,-14.025 h3
Top Solder:
  region: 16.35,9.525 16.35,13.025 13.85,13.025 13.85,9.525
  text ".Layer_Name" at 2.901,-14.073 h3
  text ".GTS" at 44.596,-14.073 h3
Bottom Solder:
  region: 16.35,9.525 16.35,13.025 13.85,13.025 13.85,9.525
  text ".GBS" at 33.311,-14.1 h3
  text ".Layer_Name" at 74.625,-14.1 h3
M1-Board Shape:
  the board outline again, w0.1
M2-Board Dimensions:
  text ".Layer_Name" at 2.903,-14.008 h3
  text ".GM2" at 44.598,-14.008 h3
M14-Top Assembly:
  text ".Layer_Name" at 2.903,-14.008 h3
  text ".GM14" at 44.598,-14.008 h3
M15-Bottom Assembly:
  text ".GM15" at 33.395,-14.04 h3
  text ".Layer_Name" at 74.709,-14.04 h3
Drill Drawing:
  drawing of 255 lines, arcs and shapes, not listed
  text "PCB SPECIFICATIONS :" at -5.575,102.429 h3
  text "PCB : TYPE 3" at 142.837,102.197 h3
  text "A.   MATERIAL :" at -5.575,98.429 h3
  text "FR-4" at 32.925,98.429 h3
  text "TG-170" at 49.425,98.429 h3
  text "X  TG-150" at 67.675,98.429 h3
  text "TG-140" at 83.675,98.429 h3
  text "ASPECT-RATIO, AXE Z :" at 142.837,96.697 h3
  text "B.   MATERIAL FAMILY :" at -5.575,95.429 h3
  text "N/A" at 32.925,95.429 h3
  text "C.   SOLDERMASK COLOR :" at -5.575,92.429 h3
  text "GREEN" at 32.925,92.429 h3
  text "WHITE" at 49.425,92.429 h3
  text "X  BLUE" at 67.675,92.429 h3
  text "BLACK" at 83.675,92.429 h3
  text "6:1 to 8:1 / LEVEL \"B\"" at 142.855,89.949 h3
  text "D.   SILKSCREEN COLOR :" at -5.575,89.429 h3
  text "X  WHITE" at 32.925,89.429 h3
  text "YELLOW" at 49.425,89.429 h3
  text "BLACK" at 67.675,89.429 h3
  text "Blue ink PANTONE 2955" at 83.675,89.429 h3
  text "E.   SURFACE FINISH :" at -5.575,86.429 h3
  text "X  ENIG" at 32.925,86.429 h3
  text "IMMERSION SILVER" at 49.425,86.429 h3
  text "IMMERSION TIN" at 83.675,86.429 h3
  text "MINIMUM PARAMETERS" at 142.882,84.348 h3
  text "HASL" at 32.925,83.429 h3
  text "HASL (PB-FREE)" at 49.425,83.429 h3
  text "GOLDEN FINGER" at 83.675,83.429 h3
  text "F.   IMPEDANCE CONTROL :" at -5.575,80.429 h3
  text "NO" at 32.925,80.429 h3
  text "X  YES  (SEE IMPEDANCE TABLE FOR DETAIL INFORMATION)" at 49.425,80.429 h3
  text "DEFAULT" at 142.882,78.848 h3
  text "G.   THROUGH VIA :" at -5.575,77.429 h3
  text "PLUG THE VIAS WHICH ARE COVERED WITH SOLDERMASK ONE OR TWO SIDE." at 32.925,77.429 h3
  text "PLUG MATERIAL :" at 32.925,74.429 h3
  text "X  SOLDERMASK" at 58.425,74.429 h3
  text "NON-CONDUCTIVE EPOXY." at 83.675,74.429 h3
  text "TRACKS : 0.2mm           / GAPS : 0.2mm" at 142.882,73.098 h3
  text "H.   STACK-UP :" at -5.575,71.429 h3
  text "SEE LAYER STACK-UP SEQUENCE FOR OVERALL THICKNESS." at 32.925,71.429 h3
  text "Layer" at 70.338,59.177 h1.52
  text "Name" at 76.713,59.177 h1.52
  text "Material" at 89.036,59.177 h1.52
  text "Thickness" at 100.11,59.177 h1.52
  text "Constant" at 109.208,59.177 h1.52
  text "Board Layer Stack" at 117.629,59.177 h1.52
  text "Top Overlay" at 76.713,56.129 h1.52
  text "Top Solder" at 76.713,53.081 h1.52
  text "Solder Resist" at 89.036,53.081 h1.52
  text "0.59mil" at 100.11,53.081 h1.52
  text "3.5" at 109.208,53.081 h1.52
  text "1" at 70.338,50.033 h1.52
  text "Top Layer" at 76.713,50.033 h1.52
  text "1.38mil" at 100.11,50.033 h1.52
  text "Dielectric 1" at 76.713,46.985 h1.52
  text "FR-4" at 89.036,46.985 h1.52
  text "59.06mil" at 100.11,46.985 h1.52
  text "4.8" at 109.208,46.985 h1.52
  text "2" at 70.337,43.937 h1.52
  text "Bottom Layer" at 76.713,43.937 h1.52
  text "1.38mil" at 100.11,43.937 h1.52
  text "Bottom Solder" at 76.713,40.889 h1.52
  text "Solder Resist" at 89.036,40.889 h1.52
  text "0.59mil" at 100.11,40.889 h1.52
  text "3.5" at 109.208,40.889 h1.52
  text "Bottom Overlay" at 76.713,37.841 h1.52
  text "Symbol" at 70.441,22.983 h1.83
  text "Count" at 77.603,22.983 h1.83
  text "Hole Size" at 84.93,22.983 h1.83
  text "Plated" at 98.827,22.983 h1.83
  text "Hole Type" at 105.116,22.983 h1.83
  text "Drill Layer Pair" at 114.269,22.983 h1.83
  text "Via/Pad" at 131.592,22.983 h1.83
  text "Pad Shape" at 139.093,22.983 h1.83
  text "146" at 77.603,19.829 h1.52
  text "0.300mm (11.81mil)" at 84.93,19.829 h1.52
  text "PTH" at 98.827,19.829 h1.52
  text "Round" at 105.116,19.829 h1.52
  text "Top Layer - Bottom Layer" at 114.269,19.829 h1.52
  text "Via" at 131.592,19.829 h1.52
  text "Rounded" at 139.093,19.829 h1.52
  text "42" at 77.603,16.675 h1.52
  text "1.000mm (39.37mil)" at 84.93,16.675 h1.52
  text "PTH" at 98.827,16.675 h1.52
  text "Round" at 105.116,16.675 h1.52
  text "Top Layer - Bottom Layer" at 114.269,16.675 h1.52
  text "Pad" at 131.592,16.675 h1.52
  text "(Mixed)" at 139.093,16.675 h1.52
  text "188 Total" at 77.603,13.521 h1.52
  text ".Layer_Name" at 2.903,-14.008 h3
  text ".DRL" at 44.598,-14.008 h3
M20-Top Title Box:
  circle w0.254: c80.908,-20.729 r1.3
  region: 66.43,-21.822 55.674,-21.822 56.667,-19.329 64.525,-19.329 64.973,-18.57 67.182,-21.118
  region: 80.433,-13.492 64.906,-13.492 64.211,-15.268 63.001,-16.493 61.604,-14.633 61.604,-12.982 62.747,-11.585 64.183,-11.206 80.433,-11.206
  lines w0.254: 56.667,-19.329 65.459,-19.329 62.393,-15.791 cw(c64.196,-13.847) 64.437,-11.206 81.201,-11.206 80.439,-13.492 ; 59.981,-10.959 cw(c62.407,-11.93) 62.643,-9.327 ; 60.02,-10.927 55.674,-21.822 74.996,-21.822 ccw(c75.245,-19.087) 77.794,-20.107 ; 61.76,-14.861 67.182,-21.118 ; 62.014,-14.861 67.319,-20.983 ; 62.014,-14.607 67.319,-20.729 ; 62.112,-13.492 75.105,-13.492 ; 62.141,-14.48 67.446,-20.602 ; 62.268,-14.353 67.573,-20.475 ; 62.395,-14.226 67.7,-20.348 ; 62.522,-14.099 67.827,-20.221 ; 62.576,-12.147 67.881,-18.268 ; 62.645,-9.327 82.094,-9.327 77.795,-20.105 ; 62.649,-13.972 67.899,-20.031 ; 62.649,-13.718 67.954,-19.84 ; 62.649,-13.464 67.954,-19.586 ; 62.649,-12.575 67.954,-18.697 ; 62.776,-13.337 68.081,-19.459 ; 62.776,-12.956 68.081,-19.078 ; 64.147,-19.342 ccw(c64.252,-18.807) 64.55,-18.35 ; 65.234,-13.479 ccw(c65.208,-14.046) 64.878,-14.508 67.242,-17.237 cw(c65.439,-19.181) 66.171,-21.729 ; 71.515,-21.618 74.404,-13.238 ; 71.737,-21.568 74.607,-13.247 ; 71.864,-21.568 74.734,-13.247 ; 72.118,-21.568 74.988,-13.247 ; 72.372,-21.568 75.242,-13.247 ; 72.626,-21.568 75.496,-13.247 ; 72.88,-21.568 75.75,-13.247 ; 73.134,-21.568 76.004,-13.247 ; 73.388,-21.568 76.258,-13.247 ; 73.642,-21.568 76.512,-13.247 ; 73.851,-21.618 76.74,-13.238 ; 76.74,-13.492 80.433,-13.492 ; 79.765,-13.49 80.527,-11.204 ; 79.931,-13.492 80.693,-11.206 ; 80.185,-13.492 80.947,-11.206
  lines w0.3: -6.097,-20.708 53.903,-20.708 ; -6.097,-15.708 53.903,-15.708 ; -6.097,-10.708 53.903,-10.708 ; 33.903,-25.708 33.903,-10.708 ; 53.903,-25.708 53.903,-5.708 ; 71.515,-21.618 73.851,-21.618 ; -6.097,-25.708 83.903,-25.708 83.903,-5.708 -6.097,-5.708 -6.096,-25.708
  text "Project: '.Board_Name'" at -5.097,-8.924 h3
  text "Layer:" at -5.096,-14.008 h3
  text "Gerber:" at 34.892,-14.008 h3
  text "Variant: '.VariantName'" at -5.097,-19.008 h3
  text "'.Board_Reference'" at 35.019,-19.008 h3
  text "R" at 80.4,-21.491 h1.52
  text "Date: '.Board_Document_Date'" at -5.097,-24.008 h3
  text "Rev: '.Board_PCB_Revision'" at 34.962,-24.008 h3
M21-Bottom Title Box:
  circle w0.254: c-2.914,-20.729 r1.3
  region: -2.439,-13.492 13.088,-13.492 13.782,-15.268 14.993,-16.493 16.39,-14.633 16.39,-12.982 15.247,-11.585 13.811,-11.206 -2.439,-11.206
  region: 11.564,-21.822 22.32,-21.822 21.327,-19.329 13.469,-19.329 13.02,-18.57 10.812,-21.118
  lines w0.254: -2.953,-11.206 -2.191,-13.492 ; -2.699,-11.206 -1.937,-13.492 ; -2.533,-11.204 -1.771,-13.49 ; -2.445,-13.492 -3.207,-11.206 13.557,-11.206 cw(c13.797,-13.847) 15.601,-15.791 12.535,-19.329 21.327,-19.329 ; -2.439,-13.492 1.253,-13.492 ; 0.199,-20.105 -4.101,-9.327 15.349,-9.327 ; 0.2,-20.107 ccw(c2.749,-19.087) 2.997,-21.822 22.32,-21.822 17.974,-10.927 ; 1.253,-13.238 4.143,-21.618 ; 1.482,-13.247 4.351,-21.568 ; 1.736,-13.247 4.605,-21.568 ; 1.99,-13.247 4.859,-21.568 ; 2.244,-13.247 5.113,-21.568 ; 2.498,-13.247 5.367,-21.568 ; 2.752,-13.247 5.621,-21.568 ; 2.889,-13.492 15.882,-13.492 ; 3.006,-13.247 5.875,-21.568 ; 3.26,-13.247 6.129,-21.568 ; 3.387,-13.247 6.256,-21.568 ; 3.589,-13.238 6.479,-21.618 ; 9.913,-19.459 15.218,-13.337 ; 9.913,-19.078 15.218,-12.956 ; 10.04,-19.84 15.345,-13.718 ; 10.04,-19.586 15.345,-13.464 ; 10.04,-18.697 15.345,-12.575 ; 10.095,-20.031 15.345,-13.972 ; 10.112,-18.268 15.417,-12.147 ; 10.167,-20.221 15.472,-14.099 ; 10.294,-20.348 15.599,-14.226 ; 10.421,-20.475 15.726,-14.353 ; 10.548,-20.602 15.853,-14.48 ; 10.675,-20.983 15.98,-14.861 ; 10.675,-20.729 15.98,-14.607 ; 10.812,-21.118 16.234,-14.861 ; 11.822,-21.729 cw(c12.555,-19.181) 10.751,-17.237 13.116,-14.508 ccw(c12.786,-14.046) 12.76,-13.479 ; 13.444,-18.35 ccw(c13.741,-18.807) 13.846,-19.342 ; 15.35,-9.327 cw(c15.587,-11.93) 18.013,-10.959
  lines w0.3: 4.143,-21.618 6.479,-21.618 ; 23.903,-25.708 23.903,-5.708 ; 23.903,-20.708 83.903,-20.708 ; 23.903,-15.708 83.903,-15.708 ; 23.903,-10.708 83.903,-10.708 ; 43.903,-25.708 43.903,-10.708 ; -6.097,-25.708 -6.097,-5.708 83.903,-5.708 83.903,-25.708 -6.097,-25.708
  text "Project: '.Board_Name'" at 82.709,-8.924 h3
  text "Gerber:" at 42.72,-14.008 h3
  text "Layer:" at 82.709,-14.008 h3
  text "'.Board_Reference'" at 42.72,-19.008 h3
  text "Variant: '.VariantName'" at 82.709,-19.008 h3
  text "R" at -2.406,-21.491 h1.52
  text "Rev: '.Board_PCB_Revision'" at 42.777,-24.008 h3
  text "Date: '.Board_Document_Date'" at 82.709,-24.008 h3

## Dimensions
0,58.3 to 60,58.3 on M2-Board Dimensions
1,0 to 1,59.3 on M2-Board Dimensions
